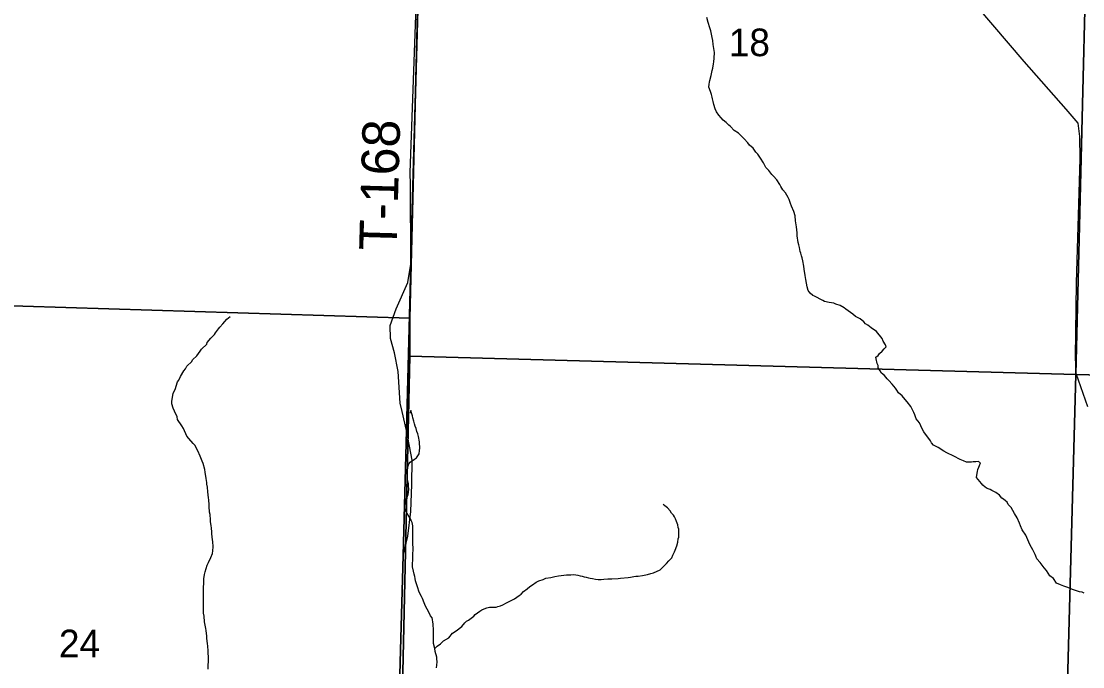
# Model space of a CAD drawing. Extents: x 1310247 to 1552180, y 377264 to 706493.
# Drawn here: x 1342366 to 1350859, y 495782 to 500950 of the extents above; entities that cross this region are included whole.
import ezdxf

# ---------------------------------------------------------------- set-up
doc = ezdxf.new("R2010")
doc.units = 0
for name, color, linetype in [('GM_X_County_Road', 7, 'Continuous'), ('GM_X_Minor_River', 7, 'Continuous'), ('GM_X_Section', 7, 'Continuous'), ('GM_X_Section_Text', 7, 'Continuous'), ('GM_X_Township', 7, 'Continuous'), ('GM_X_Township_Road', 7, 'Continuous'), ('GM_X_Township_Road_Text', 7, 'Continuous')]:
    doc.layers.add(name, color=color, linetype=linetype)

msp = doc.modelspace()

# ---------------------------------------------------------------- linework, layer by layer
at = {"layer": 'GM_X_County_Road'}
msp.add_lwpolyline([(1347548, 503816.3), (1347666.4, 503708.9), (1347804.8, 503582.9), (1347902.7, 503496.8), (1348056.7, 503335.6), (1348402.4, 502947.3), (1348716.8, 502556.3), (1349076.5, 502141.7), (1349438.5, 501735), (1349761.8, 501363.8), (1350388.4, 500628.2), (1350723.2, 500246.5), (1350819.4, 500134.6), (1350832.4, 500027.5), (1350834.9, 499848), (1350804.9, 498855.4), (1350797.4, 498261.9), (1350802.4, 498132.2), (1350895.4, 497865.2)], dxfattribs=at)
at = {"layer": 'GM_X_Minor_River'}
for points in [[(1347947.8, 500198), (1347928.5, 500224.7), (1347917.2, 500249.1), (1347908.2, 500283.5), (1347902.9, 500307.7), (1347897.4, 500327.9), (1347893.8, 500342), (1347888.5, 500364.3), (1347882.9, 500380.5), (1347871.7, 500408.9), (1347868.1, 500423), (1347868.8, 500447.1), (1347873.3, 500463), (1347875.7, 500476.9), (1347884.8, 500514.8), (1347894, 500554.6), (1347898.6, 500574.5), (1347903.6, 500608.5), (1347908.1, 500624.4), (1347911, 500654.4), (1347912.3, 500698.5), (1347907.2, 500732.7), (1347902.1, 500763), (1347899.1, 500797.1), (1347893.7, 500819.3), (1347883.2, 500873.8), (1347875.9, 500896.1), (1347861, 500938.7), (1347850.2, 500981.1)], [(1349552.1, 497735.6), (1349527, 497768.4), (1349515.8, 497798.8), (1349508.3, 497817.1), (1349483.6, 497866), (1349454.6, 497902.9), (1349439.1, 497921.4), (1349413.9, 497952.3), (1349384.4, 497975.2), (1349371.1, 497997.7), (1349361.4, 498012), (1349334.3, 498044.9), (1349307, 498073.8), (1349293.3, 498086.2), (1349272, 498112.9), (1349248.6, 498133.7), (1349237.1, 498152.1), (1349221.7, 498174.6), (1349222.2, 498194.6), (1349214.7, 498210.9), (1349205.7, 498247.3), (1349204.1, 498261.4), (1349222.6, 498274.8), (1349233.1, 498290.6), (1349253.6, 498308), (1349270.3, 498327.6), (1349284.8, 498343.2), (1349281.2, 498359.3), (1349262, 498388), (1349252.6, 498410.3), (1349208.1, 498465.8), (1349166.8, 498495.1), (1349139.3, 498516), (1349121.6, 498528.5), (1349107.9, 498543), (1349078.6, 498567.9), (1349041, 498587.1), (1349019.5, 498605.8), (1348962.4, 498645.6), (1348948.7, 498656), (1348917.1, 498675), (1348883.3, 498686.1), (1348867.4, 498692.5), (1348829.5, 498699.7), (1348793.6, 498706.8), (1348779.7, 498713.2), (1348712.5, 498749.3), (1348698.7, 498755.7), (1348679.1, 498772.4), (1348661.7, 498795), (1348654.5, 498825.2), (1348644.1, 498881.7), (1348639, 498913.9), (1348630.5, 498966.3), (1348627.2, 498990.5), (1348620.4, 499032.8), (1348613.1, 499057.1), (1348609.6, 499073.3), (1348604.1, 499093.5), (1348598.5, 499107.7), (1348591.4, 499138), (1348588, 499160.1), (1348582.5, 499178.4), (1348574.1, 499232.8), (1348572.7, 499254.9), (1348568.1, 499305.1), (1348563.1, 499337.4), (1348561.5, 499351.5), (1348558.6, 499391.7), (1348547.6, 499428.1), (1348528.8, 499470.8), (1348521.4, 499491), (1348510.3, 499523.5), (1348500.7, 499539.8), (1348481.7, 499576.5), (1348458.3, 499601.2), (1348443.1, 499627.8), (1348435.5, 499642), (1348410.5, 499680.9), (1348385.2, 499709.7), (1348371.6, 499724.1), (1348348.4, 499754.9), (1348323, 499779.7), (1348311.6, 499800.1), (1348304, 499816.4), (1348281, 499853.2), (1348257.9, 499886), (1348244.3, 499902.4), (1348221.2, 499935.2), (1348191.8, 499958.1), (1348180.2, 499976.5), (1348151.1, 500009.5), (1348129.6, 500030.2), (1348104.2, 500053), (1348070.7, 500076), (1348041.5, 500107), (1348027.8, 500117.4), (1348006.4, 500140.1), (1347982.8, 500156.9), (1347965.3, 500177.5), (1347947.8, 500198)], [(1343870.4, 497064.6), (1343868.8, 497078.7), (1343866, 497118.9), (1343864.4, 497135), (1343857.8, 497183.3), (1343854.9, 497219.5), (1343851.6, 497243.7), (1343852, 497257.7), (1343844.9, 497290), (1343838.3, 497340.4), (1343834.9, 497360.5), (1343822.3, 497409), (1343812.7, 497427.4), (1343797.9, 497467.9), (1343779.1, 497510.6), (1343754.3, 497555.5), (1343740.6, 497569.9), (1343705.7, 497609.1), (1343692.2, 497629.5), (1343663.9, 497690.5), (1343650.4, 497711), (1343615.8, 497762.2), (1343612.4, 497782.3), (1343591.6, 497829.1), (1343582.3, 497851.4), (1343571.3, 497887.8), (1343569.8, 497905.9), (1343581.7, 497971.8), (1343596.7, 498001.4), (1343616.5, 498063), (1343626.9, 498076.7), (1343639.9, 498106.4), (1343667.3, 498151.7), (1343679.8, 498167.4), (1343690.4, 498189.1), (1343731.7, 498226), (1343736.1, 498239.9), (1343771.1, 498271), (1343796.3, 498308.3), (1343808.8, 498326), (1343850.1, 498364.8), (1343854.5, 498378.8), (1343881.6, 498412), (1343912.6, 498443.2), (1343921, 498457), (1343944, 498486.4), (1343954.4, 498500.1), (1343979.3, 498527.5), (1344010.5, 498564.6), (1344037.2, 498585.9)], [(1345451.8, 497334.3), (1345452.3, 497350.3), (1345461.5, 497390.1), (1345466, 497408.1), (1345478.5, 497421.7), (1345513.3, 497444.8), (1345527.6, 497454.4), (1345540.1, 497470), (1345548.6, 497485.8), (1345553.4, 497513.8), (1345553.9, 497531.8), (1345554.4, 497547.8), (1345552.8, 497561.9), (1345551.4, 497582), (1345544.6, 497626.3), (1345539.2, 497646.5), (1345531.8, 497666.8), (1345524.4, 497689.1), (1345517, 497709.4), (1345513.5, 497727.5), (1345508, 497747.8), (1345498.8, 497776.1), (1345495.2, 497790.3), (1345489.7, 497808.5), (1345482.4, 497832.8), (1345477.9, 497814.8), (1345477.5, 497813.6)], [(1350869.2, 496370.6), (1350853.4, 496379.1), (1350833.4, 496381.7), (1350793.6, 496394.9), (1350775.7, 496401.5), (1350740.1, 496416.6), (1350708.3, 496427.6), (1350680.5, 496438.4), (1350648.7, 496451.4), (1350623.7, 496488.2), (1350594.3, 496511.2), (1350569.4, 496552), (1350550, 496574.7), (1350519.1, 496617.7), (1350491.8, 496646.6), (1350482.4, 496666.9), (1350476.8, 496681.1), (1350459.9, 496719.8), (1350438.8, 496756.5), (1350427.5, 496780.9), (1350403, 496835.8), (1350374.2, 496878.8), (1350361.1, 496911.2), (1350353.6, 496931.5), (1350334.8, 496974.2), (1350313.7, 497008.9), (1350285, 497057.9), (1350261.7, 497082.7), (1350254.1, 497098.9), (1350240.4, 497111.4), (1350224.7, 497123.9), (1350210.9, 497132.3), (1350191.5, 497155), (1350162.1, 497177.9), (1350132.4, 497192.8), (1350118.6, 497201.2), (1350094.8, 497210), (1350077, 497220.5), (1350059.4, 497235.1), (1350047.8, 497249.5), (1350022.6, 497282.3), (1350009, 497296.8), (1350011.6, 497316.8), (1350016.4, 497344.7), (1350018.9, 497360.7), (1350027.5, 497380.5), (1350033.9, 497394.3), (1350040.5, 497414.2), (1350020.7, 497424.8), (1350002.6, 497423.3), (1349982.5, 497421.9), (1349968.4, 497420.3), (1349928.3, 497421.5), (1349904.6, 497432.2), (1349878.7, 497441), (1349827.3, 497468.6), (1349771.9, 497494.4), (1349746.2, 497509.2), (1349702.9, 497536.5), (1349665.3, 497557.7), (1349649.8, 497576.2), (1349640.2, 497590.5), (1349586.2, 497664.3), (1349574.8, 497686.8), (1349552.1, 497735.6)], [(1345689.4, 495772.9), (1345692, 495794.9), (1345692.9, 495822.9), (1345691.5, 495845), (1345689.9, 495859.1), (1345677.1, 495903.6), (1345673.8, 495927.8), (1345665, 495970.1), (1345663.5, 495988.2), (1345663.1, 496042.4), (1345664.6, 496092.5), (1345663, 496106.6), (1345661.6, 496126.7), (1345660, 496140.8), (1345656.5, 496160.9), (1345652.9, 496175.1), (1345641.3, 496189.5), (1345631.8, 496207.8), (1345614.8, 496244.4), (1345601.5, 496268.9), (1345590.1, 496293.3), (1345577.1, 496327.8), (1345567.5, 496344.1), (1345550.5, 496380.7), (1345535.7, 496423.3), (1345532.1, 496437.4), (1345521, 496469.8), (1345517.6, 496490), (1345514, 496504.1), (1345508.5, 496524.3), (1345503.2, 496546.6), (1345496.2, 496582.9), (1345500.9, 496743.2), (1345499.3, 496757.3), (1345498.6, 496803.4), (1345499.2, 496825.5), (1345498.1, 496853.6), (1345498.6, 496871.6), (1345499.7, 496909.7), (1345494.5, 496937.9), (1345486.9, 496952.2), (1345477.4, 496972.5), (1345465.8, 496986.9), (1345454.4, 497009.3), (1345441.1, 497033.8), (1345435.6, 497054), (1345434.2, 497072.1), (1345439.1, 497102), (1345445.6, 497119.9), (1345456.4, 497147.6), (1345460.9, 497161.5), (1345463.4, 497179.5), (1345466.1, 497203.5), (1345464.9, 497231.6), (1345463.4, 497247.7), (1345454.6, 497292.1), (1345453.1, 497310.2), (1345451.8, 497334.3)], [(1343860.6, 495763.3), (1343863.4, 495857.5), (1343860.5, 495895.7), (1343860.9, 495909.7), (1343858, 495947.9), (1343856.6, 495968), (1343851.7, 496008.3), (1343850.3, 496028.4), (1343845.6, 496072.6), (1343842, 496088.8), (1343835.2, 496129.1), (1343831.6, 496143.2), (1343828.8, 496187.4), (1343825.5, 496211.6), (1343823.6, 496283.9), (1343824.6, 496317.9), (1343824.5, 496382.1), (1343827.5, 496486.3), (1343832.6, 496522.3), (1343837.2, 496542.2), (1343854.8, 496595.8), (1343865.4, 496617.5), (1343882.7, 496657.1), (1343895.6, 496688.8), (1343898.3, 496710.8), (1343901.2, 496742.8), (1343898.4, 496785), (1343896.8, 496799.1), (1343892.1, 496845.4), (1343890.5, 496859.5), (1343887.6, 496895.6), (1343886, 496909.7), (1343881, 496946), (1343879.4, 496960.1), (1343876.6, 497002.3), (1343873.2, 497020.4), (1343870.4, 497064.6)], [(1345673.8, 495927.8), (1345673.8, 495927.8), (1345692.5, 495947.3), (1345719.1, 495966.5), (1345743.9, 495989.8), (1345786.7, 496014.6), (1345815.9, 496051.9), (1345846.5, 496069), (1345889.7, 496103.8), (1345914.6, 496133.2), (1345927.1, 496146.8), (1345943.4, 496156.4), (1345986.5, 496187.2), (1345998.9, 496200.9), (1346035.8, 496227.8), (1346052.2, 496239.4), (1346068.5, 496246.9), (1346090.8, 496254.3), (1346113, 496259.6), (1346135.1, 496261), (1346165.2, 496260.1), (1346179.4, 496263.7), (1346199.6, 496269.1), (1346217.9, 496278.6), (1346248.5, 496293.7), (1346275, 496306.9), (1346311.6, 496325.9), (1346348.5, 496352.9), (1346367, 496364.4), (1346383.6, 496383.9), (1346414.4, 496407.1), (1346434.9, 496424.5), (1346457.4, 496437.9), (1346486.1, 496459.1), (1346506.5, 496470.5), (1346543, 496481.5), (1346563.3, 496490.9), (1346603.7, 496497.7), (1346636, 496504.8), (1346664.2, 496509.9), (1346706.5, 496514.7), (1346728.7, 496518), (1346762.8, 496519), (1346785, 496520.4), (1346803, 496517.8), (1346818.9, 496515.3), (1346836.9, 496510.8), (1346854.9, 496508.2), (1346870.8, 496503.8), (1346884.7, 496499.3), (1346904.6, 496494.7), (1346918.6, 496492.3), (1346936.6, 496489.8), (1346960.6, 496485), (1346982.6, 496482.4), (1347004.6, 496481.7), (1347026.7, 496483.1), (1347058.9, 496486.1), (1347091.1, 496487.2), (1347141.3, 496489.7), (1347159.4, 496491.1), (1347221.9, 496497.3), (1347240, 496500.8), (1347268.2, 496504), (1347284.4, 496507.5), (1347302.4, 496507), (1347336.7, 496511.9), (1347377.1, 496520.8), (1347403.4, 496530), (1347423.6, 496533.4), (1347476.5, 496557.9), (1347499.2, 496579.3), (1347528.2, 496608.5), (1347546.9, 496630), (1347571.7, 496655.3), (1347580.3, 496675.2), (1347593.1, 496702.8), (1347597.6, 496716.8), (1347610.6, 496750.5), (1347619.5, 496780.3), (1347622.2, 496806.3), (1347626.7, 496820.2), (1347627.9, 496862.3), (1347626.5, 496884.4), (1347622.9, 496898.5), (1347619.5, 496918.7), (1347608.2, 496945.1), (1347600.8, 496967.4), (1347591.2, 496981.7), (1347583.6, 496996), (1347568, 497012.5), (1347556.5, 497030.8), (1347535.2, 497055.6), (1347515.5, 497070.2), (1347501.8, 497080.6)]]:
    msp.add_lwpolyline(points, dxfattribs=at)
at = {"layer": 'GM_X_Section'}
for points in [[(1345608.2, 503901.4), (1345600.4, 503579.5), (1345474.9, 498571.8), (1340312, 498733.1), (1340450.8, 504038.6)], [(1350935.3, 503418), (1350802.7, 498122.5), (1345475.5, 498269.8), (1345474.9, 498571.8), (1345600.4, 503579.5)], [(1355120.9, 503300.4), (1355014.7, 498016.2), (1350802.7, 498122.5), (1350935.3, 503418)], [(1345475.5, 498269.8), (1345365.6, 493329.7), (1340178.9, 493497.3), (1340312, 498733.1), (1345474.9, 498571.8)], [(1350802.7, 498122.5), (1350661.9, 492897.1), (1345354.9, 492967.9), (1345365.6, 493329.7), (1345475.5, 498269.8)], [(1355014.7, 498016.2), (1354901.1, 492842.3), (1350661.9, 492897.1), (1350802.7, 498122.5)]]:
    msp.add_lwpolyline(points, close=True, dxfattribs=at)
at = {"layer": 'GM_X_Township'}
for points in [[(1345712.4, 507978.5), (1345674.3, 506485.7), (1345654.2, 505589.5), (1345643.1, 505191.7), (1345632.2, 504589.3), (1345613.2, 503974.3), (1345591.9, 503070.1), (1345592.6, 502922.9), (1345482.9, 499065.7), (1345483.3, 499004.2), (1345447.4, 497673.5), (1345421.6, 496672.9), (1345401.6, 495914.5), (1345378.7, 495124)], [(1345378.7, 495124), (1345401.6, 495914.5), (1345421.6, 496672.9), (1345447.4, 497673.5), (1345483.3, 499004.2), (1345482.9, 499065.7), (1345592.6, 502922.9), (1345591.9, 503070.1), (1345613.2, 503974.3), (1345632.2, 504589.3), (1345643.1, 505191.7), (1345654.2, 505589.5), (1345674.3, 506485.7), (1345712.4, 507978.5)]]:
    msp.add_lwpolyline(points, dxfattribs=at)
at = {"layer": 'GM_X_Township_Road'}
for points in [[(1345479.2, 499640.6), (1345478.5, 499739.2), (1345592.6, 502922.9), (1345591.9, 503070.2)], [(1345378.7, 495124), (1345401.6, 495914.5), (1345421.6, 496672.9), (1345460.2, 496828.4), (1345484, 497024.5), (1345492.3, 497241.1), (1345493.9, 497435.8), (1345447.4, 497673.5), (1345413, 497824.7), (1345396.8, 497892.3), (1345382.1, 498145.8), (1345352.4, 498295.2), (1345319.6, 498410.6), (1345316.6, 498515.1), (1345364.6, 498648.2), (1345459, 498858.3), (1345483.3, 499004.2), (1345482.9, 499065.7), (1345479.5, 499601.7), (1345479.2, 499640.6)]]:
    msp.add_lwpolyline(points, dxfattribs=at)

# ---------------------------------------------------------------- texts
at = {"layer": 'GM_X_Section_Text'}
for s, p in [('18', (1348027.1, 500670.4)), ('24', (1342667.9, 495858.5))]:
    msp.add_text(s, height=221, rotation=0.00001, dxfattribs=at).set_placement(p)
at = {"layer": 'GM_X_Township_Road_Text'}
msp.add_text('T-168', height=300, rotation=88.40207, dxfattribs=at).set_placement((1345368.8, 499111.4))

doc.saveas('drawing.dxf')
